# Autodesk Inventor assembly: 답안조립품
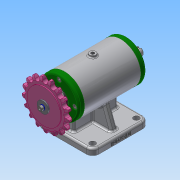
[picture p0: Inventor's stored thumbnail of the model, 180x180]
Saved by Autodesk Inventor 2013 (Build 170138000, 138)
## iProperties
Created: 2019-06
Part Number: 답안조립품
Document SubType Name: Assembly
Designer: Administrator
Author: Administrator
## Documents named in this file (11)
- C:\Users\Administrator\Desktop\490604V1023\답안조립품.iam
- C:\Users\Administrator\Desktop\490604V1023\본체.ipt
- C:\Users\Administrator\Desktop\490604V1023\베어링 6203.ipt
- C:\Users\Administrator\Desktop\490604V1023\볼트 M4.ipt
- C:\Users\Administrator\Desktop\490604V1023\스프로킷.ipt
- C:\Users\Administrator\Desktop\490604V1023\스프링와셔.ipt
- C:\Users\Administrator\Desktop\490604V1023\오일 실 17 30 5.ipt
- C:\Users\Administrator\Desktop\490604V1023\축.ipt
- C:\Users\Administrator\Desktop\490604V1023\커버.ipt
- C:\Users\Administrator\Desktop\490604V1023\키 4x4x12.ipt
- C:\Users\Administrator\Desktop\490604V1023\평와셔.ipt
